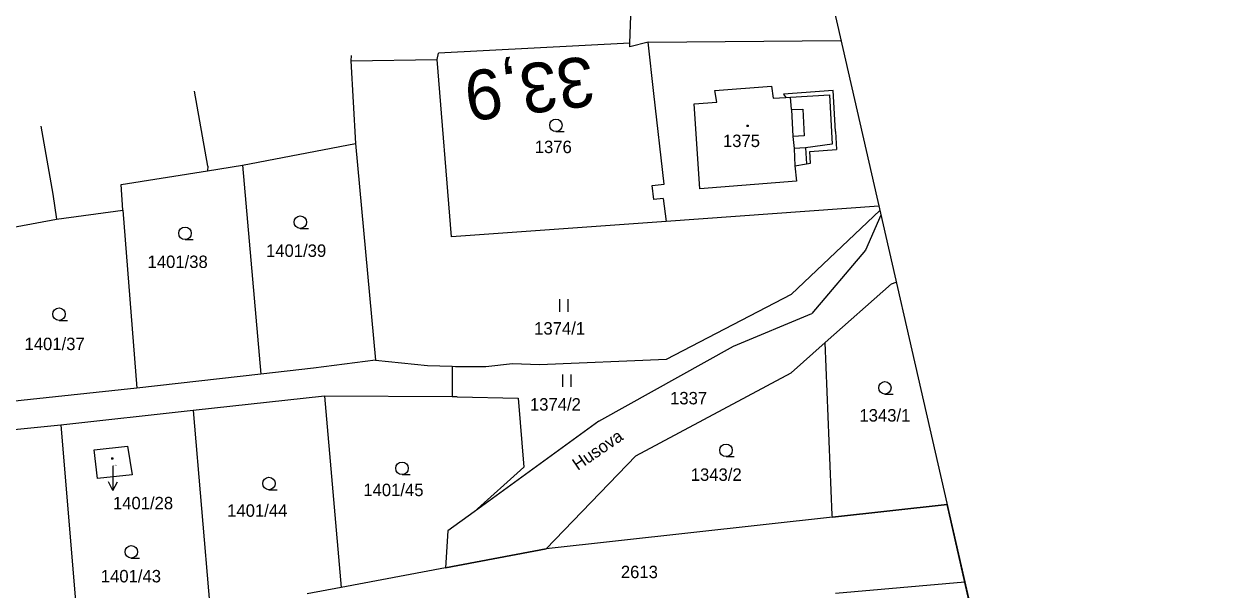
# Model space of a CAD drawing. Extents: x -805730 to -804640, y -1150889 to -1150366.
# Drawn here: x -804785.9 to -804640.4, y -1150515.7 to -1150447.5 of the extents above; entities that cross this region are included whole.
import ezdxf

# ---------------------------------------------------------------- set-up
doc = ezdxf.new("R2010")
doc.units = 0
for name, color, linetype in [('Default', 7, 'Continuous'), ('formát', 7, 'Continuous'), ('kilometráž - vrstava 7', 7, 'Continuous'), ('kn_celek - Cisla parcel pomocna', 7, 'Continuous'), ('kn_celek - Cisla pozemkovych parcel', 7, 'Continuous'), ('kn_celek - Cisla stavebnich parcel', 7, 'Continuous'), ('kn_celek - Dalsi prvky mapy popis', 7, 'Continuous'), ('kn_celek - Hranice parcel', 7, 'Continuous'), ('kn_celek - Vnitrni kresby', 7, 'Continuous'), ('kn_celek - Znacky budov', 7, 'Continuous'), ('kn_celek - Znacky kultur', 7, 'Continuous'), ('plochy - SZDC', 7, 'Continuous'), ('PSR_C2_2_trasa_Vimperk - Kabelová trasa', 7, 'Continuous')]:
    doc.layers.add(name, color=color, linetype=linetype)

# ---------------------------------------------------------------- blocks, each defined once
blk = doc.blocks.new('304')
at = {"layer": 'Default'}
blk.add_line((-0.1, 0), (9.9, 0), dxfattribs=at)
blk.add_circle((-0.1, 7.5), 7.5, dxfattribs=at)
blk = doc.blocks.new('306')
at = {"layer": 'Default'}
for p, q in [((-5.2, 0), (-5.2, 15)), ((4.8, 0), (4.8, 15))]:
    blk.add_line(p, q, dxfattribs=at)
blk = doc.blocks.new('402')
at = {"layer": 'Default'}
for p, q in [((-0.8, 0.8), (0.7, 0.8)), ((-0.8, 0.8), (-0.8, -0.7)), ((0.7, 0.8), (0.7, -0.7)), ((0.7, -0.7), (-0.8, -0.7))]:
    blk.add_line(p, q, dxfattribs=at)
blk = doc.blocks.new('Z61')
at = {"layer": 'Default'}
for p, q in [((0, 0), (30, 0)), ((30, 0), (19.2, 5.3)), ((30, 0), (19.2, -5.3))]:
    blk.add_line(p, q, dxfattribs=at)

msp = doc.modelspace()

# ---------------------------------------------------------------- linework, layer by layer
at = {"layer": 'formát'}
msp.add_line((-804706.6, -1150365.97), (-804640.43, -1150655.5), dxfattribs=at)
at = {"layer": 'kn_celek - Hranice parcel'}
for p, q in [((-804712.93, -1150449.81), (-804712.73, -1150443.56)), ((-804712.93, -1150449.81), (-804735.98, -1150451.02)), ((-804710.75, -1150449.7), (-804712.95, -1150450.24)), ((-804712.95, -1150450.24), (-804712.93, -1150449.81)), ((-804710.75, -1150449.7), (-804687.52, -1150449.47)), ((-804710.06, -1150455.87), (-804710.75, -1150449.7)), ((-804746.53, -1150451.28), (-804746.54, -1150451.93)), ((-804736.15, -1150451.78), (-804735.98, -1150451.02)), ((-804746.54, -1150451.93), (-804736.15, -1150451.78)), ((-804746.54, -1150451.93), (-804746, -1150461.9)), ((-804734.44, -1150473.15), (-804736.15, -1150451.78)), ((-804763.78, -1150464.64), (-804765.37, -1150455.59)), ((-804708.82, -1150466.81), (-804710.06, -1150455.87)), ((-804783.88, -1150459.82), (-804782.46, -1150468.02)), ((-804759.6, -1150464.51), (-804746, -1150461.9)), ((-804746, -1150461.9), (-804743.58, -1150488.04)), ((-804763.8, -1150465.18), (-804759.6, -1150464.51)), ((-804759.6, -1150464.51), (-804757.39, -1150489.7)), ((-804774.23, -1150466.84), (-804763.8, -1150465.18)), ((-804763.78, -1150464.64), (-804763.8, -1150465.18)), ((-804774.01, -1150469.95), (-804774.23, -1150466.84)), ((-804710.25, -1150466.97), (-804708.82, -1150466.81)), ((-804710.06, -1150468.67), (-804710.25, -1150466.97)), ((-804782.46, -1150468.02), (-804782.01, -1150471.04)), ((-804708.92, -1150468.54), (-804710.06, -1150468.67)), ((-804708.92, -1150468.54), (-804708.56, -1150471.29)), ((-804782.01, -1150471.04), (-804774.01, -1150469.95)), ((-804774.01, -1150469.95), (-804772.35, -1150491.38)), ((-804682.95, -1150469.44), (-804708.56, -1150471.29)), ((-804693.49, -1150480.06), (-804682.83, -1150469.99)), ((-804789.66, -1150472.44), (-804782.01, -1150471.04)), ((-804708.56, -1150471.29), (-804734.44, -1150473.15)), ((-804682.7, -1150470.54), (-804684.56, -1150474.78)), ((-804684.56, -1150474.78), (-804691.04, -1150482.4)), ((-804689.41, -1150485.9), (-804681.43, -1150478.82)), ((-804681.43, -1150478.82), (-804680.86, -1150478.61)), ((-804708.52, -1150487.91), (-804693.49, -1150480.06)), ((-804700.46, -1150486.35), (-804691.04, -1150482.4)), ((-804716.68, -1150495.36), (-804700.46, -1150486.35)), ((-804693.5, -1150489.53), (-804689.41, -1150485.9)), ((-804688.56, -1150506.71), (-804689.41, -1150485.9)), ((-804751.05, -1150489), (-804757.39, -1150489.7)), ((-804743.58, -1150488.04), (-804751.05, -1150489)), ((-804743.58, -1150488.04), (-804737.31, -1150488.66)), ((-804737.31, -1150488.66), (-804734.35, -1150488.75)), ((-804734.35, -1150488.75), (-804733.93, -1150488.77)), ((-804734.35, -1150488.75), (-804734.33, -1150492.45)), ((-804733.93, -1150488.77), (-804730.3, -1150488.79)), ((-804730.3, -1150488.79), (-804727.07, -1150488.42)), ((-804727.07, -1150488.42), (-804723.84, -1150488.54)), ((-804723.84, -1150488.54), (-804708.52, -1150487.91)), ((-804757.39, -1150489.7), (-804772.35, -1150491.38)), ((-804712.24, -1150499.55), (-804693.5, -1150489.53)), ((-804772.35, -1150491.38), (-804788.15, -1150493.09)), ((-804749.71, -1150492.36), (-804765.53, -1150494.1)), ((-804734.33, -1150492.45), (-804749.71, -1150492.36)), ((-804749.71, -1150492.36), (-804747.72, -1150515.43)), ((-804733.75, -1150492.46), (-804734.33, -1150492.45)), ((-804733.75, -1150492.46), (-804726.41, -1150492.61)), ((-804726.41, -1150492.61), (-804725.72, -1150500.94)), ((-804765.53, -1150494.1), (-804781.47, -1150495.86)), ((-804765.53, -1150494.1), (-804763.55, -1150517.73)), ((-804781.47, -1150495.86), (-804797.37, -1150497.46)), ((-804781.47, -1150495.86), (-804779.51, -1150519.42)), ((-804716.68, -1150495.36), (-804731.68, -1150506.29)), ((-804777.46, -1150498.82), (-804773.44, -1150498.4)), ((-804777.09, -1150502.3), (-804777.46, -1150498.82)), ((-804773.44, -1150498.4), (-804772.89, -1150501.85)), ((-804723.03, -1150510.78), (-804712.24, -1150499.55)), ((-804772.89, -1150501.85), (-804777.09, -1150502.3)), ((-804725.72, -1150500.94), (-804731.68, -1150506.29)), ((-804731.68, -1150506.29), (-804734.86, -1150508.61)), ((-804688.55, -1150506.95), (-804688.56, -1150506.71)), ((-804688.55, -1150506.95), (-804674.73, -1150505.41)), ((-804688.55, -1150506.95), (-804723.03, -1150510.78)), ((-804734.86, -1150508.61), (-804735.17, -1150513.06)), ((-804735.17, -1150513.06), (-804723.03, -1150510.78)), ((-804735.17, -1150513.06), (-804747.72, -1150515.43)), ((-804747.72, -1150515.43), (-804751.83, -1150516.2))]:
    msp.add_line(p, q, dxfattribs=at)
at = {"layer": 'kn_celek - Vnitrni kresby'}
for p, q in [((-804702.69, -1150455.5), (-804695.87, -1150455)), ((-804702.47, -1150456.92), (-804702.69, -1150455.5)), ((-804695.87, -1150455), (-804695.69, -1150456.44)), ((-804688.44, -1150455.5), (-804694.45, -1150455.95)), ((-804688.16, -1150460.44), (-804688.44, -1150455.5)), ((-804705.18, -1150457.11), (-804702.47, -1150456.92)), ((-804704.52, -1150467.35), (-804705.18, -1150457.11)), ((-804695.69, -1150456.44), (-804694.16, -1150456.37)), ((-804694.45, -1150455.95), (-804694.16, -1150456.37)), ((-804694.16, -1150456.37), (-804693.61, -1150456.33)), ((-804693.61, -1150456.33), (-804688.91, -1150456.02)), ((-804693.48, -1150457.82), (-804693.61, -1150456.33)), ((-804688.91, -1150456.02), (-804688.56, -1150461.98)), ((-804693.48, -1150457.82), (-804692.1, -1150457.75)), ((-804693.48, -1150457.82), (-804693.3, -1150461.06)), ((-804692.1, -1150457.75), (-804691.95, -1150460.97)), ((-804691.95, -1150460.97), (-804693.3, -1150461.06)), ((-804693.3, -1150461.06), (-804693.16, -1150462.5)), ((-804688.16, -1150460.44), (-804688.04, -1150462.61)), ((-804691.77, -1150462.41), (-804693.16, -1150462.5)), ((-804693.16, -1150462.5), (-804693.07, -1150464.61)), ((-804688.56, -1150461.98), (-804691.77, -1150462.41)), ((-804691.77, -1150462.41), (-804691.68, -1150464.36)), ((-804691.28, -1150462.87), (-804688.04, -1150462.61)), ((-804691.18, -1150464.27), (-804691.28, -1150462.87)), ((-804693.07, -1150464.61), (-804691.68, -1150464.36)), ((-804691.68, -1150464.36), (-804691.18, -1150464.27)), ((-804693.07, -1150464.61), (-804692.87, -1150466.46)), ((-804692.87, -1150466.46), (-804704.52, -1150467.35))]:
    msp.add_line(p, q, dxfattribs=at)
at = {"layer": 'plochy - SZDC'}
for p, q in [((-804674.73, -1150505.41), (-804688.55, -1150506.95)), ((-804672.1, -1150516.95), (-804674.73, -1150505.41)), ((-804688.55, -1150506.95), (-804723.03, -1150510.78)), ((-804723.03, -1150510.78), (-804735.17, -1150513.06)), ((-804735.17, -1150513.06), (-804747.72, -1150515.43)), ((-804747.72, -1150515.43), (-804751.83, -1150516.2))]:
    msp.add_line(p, q, dxfattribs=at)
at = {"layer": 'PSR_C2_2_trasa_Vimperk - Kabelová trasa'}
msp.add_line((-804688.16, -1150516.11), (-804672.6, -1150514.73), dxfattribs=at)

# ---------------------------------------------------------------- block references
at = {"layer": 'kn_celek - Cisla parcel pomocna', "xscale": 0.1, "yscale": 0.10000000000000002, "rotation": -90.00000000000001}
msp.add_blockref('Z61', (-804775.21, -1150500.75), dxfattribs=at)
at = {"layer": 'kn_celek - Znacky budov', "xscale": 0.1, "yscale": 0.10000000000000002}
for p in [(-804698.78, -1150459.79), (-804775.3, -1150499.88)]:
    msp.add_blockref('402', p, dxfattribs=at)
at = {"layer": 'kn_celek - Znacky kultur', "xscale": 0.1, "yscale": 0.10000000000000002}
for name, p in [('304', (-804721.84, -1150460.46)), ('304', (-804752.63, -1150472.14)), ('304', (-804766.52, -1150473.48)), ('304', (-804781.69, -1150483.23)), ('306', (-804720.85, -1150482.18)), ('306', (-804720.49, -1150491.24)), ('304', (-804682.21, -1150492.11)), ('304', (-804701.35, -1150499.64)), ('304', (-804740.38, -1150501.81)), ('304', (-804756.41, -1150503.64)), ('304', (-804772.99, -1150511.88))]:
    msp.add_blockref(name, p, dxfattribs=at)

# ---------------------------------------------------------------- texts
at = {"layer": 'kilometráž - vrstava 7'}
msp.add_text('33,9', height=6, rotation=187.2542, dxfattribs=at).set_placement((-804717.65, -1150451.32))
at = {"layer": 'kn_celek - Cisla parcel pomocna'}
msp.add_text('1401/28', height=1.5, dxfattribs=at).set_placement((-804775.21, -1150506))
at = {"layer": 'kn_celek - Cisla pozemkovych parcel'}
for s, p in [('1376', (-804724.4, -1150463.06)), ('1401/39', (-804756.77, -1150475.57)), ('1401/38', (-804771.04, -1150476.91)), ('1374/1', (-804724.47, -1150484.94)), ('1401/37', (-804785.86, -1150486.81)), ('1337', (-804708.1, -1150493.35)), ('1374/2', (-804724.98, -1150494.1)), ('1343/1', (-804685.29, -1150495.42)), ('1343/2', (-804705.61, -1150502.57)), ('1401/45', (-804745.05, -1150504.41)), ('1401/44', (-804761.45, -1150506.9)), ('1401/43', (-804776.67, -1150514.81)), ('2613', (-804714.03, -1150514.3))]:
    msp.add_text(s, height=1.5, dxfattribs=at).set_placement(p)
at = {"layer": 'kn_celek - Cisla stavebnich parcel'}
for s, height, p in [('1375', 1.5, (-804701.73, -1150462.33)), ('1401/28', 0.1, (-804775.21, -1150500.72))]:
    msp.add_text(s, height=height, dxfattribs=at).set_placement(p)
at = {"layer": 'kn_celek - Dalsi prvky mapy popis'}
msp.add_text('Husova', height=1.5, rotation=34.4448, dxfattribs=at).set_placement((-804719.22, -1150501.38))

doc.saveas('drawing.dxf')
